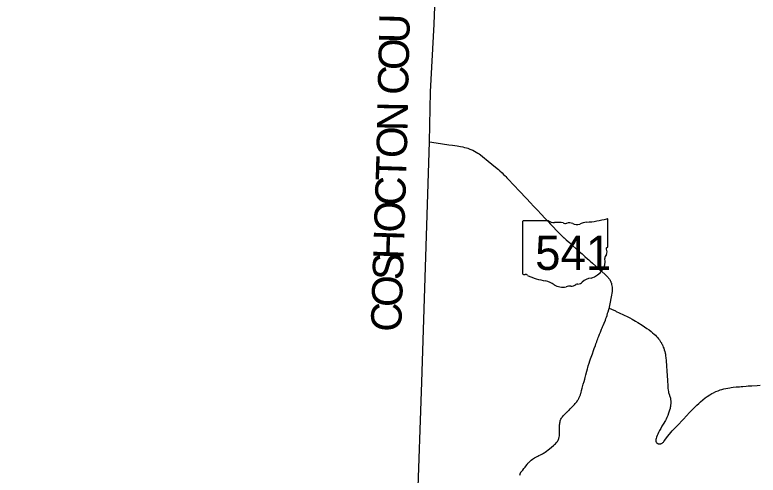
# Model space of a CAD drawing. Extents: x 1913970 to 2397567, y 78841 to 829347.
# Drawn here: x 2186978 to 2211403, y 785537 to 800656 of the extents above; entities that cross this region are included whole.
import ezdxf

# ---------------------------------------------------------------- set-up
doc = ezdxf.new("R2010")
doc.units = 0
for name, color, linetype in [('GM_X_County', 7, 'Continuous'), ('GM_X_County_Text', 7, 'Continuous'), ('GM_X_State_Location', 7, 'Continuous'), ('GM_X_State_Route', 7, 'Continuous'), ('GM_X_State_Shield', 7, 'Continuous')]:
    doc.layers.add(name, color=color, linetype=linetype)

msp = doc.modelspace()

# ---------------------------------------------------------------- linework, layer by layer
at = {"layer": 'GM_X_County'}
msp.add_lwpolyline([(2186978, 767293), (2187218, 775508), (2187296, 778812), (2187489, 783655), (2187543, 784833), (2188969, 784801), (2192356, 784732), (2196471, 784613), (2200213, 784515), (2200352, 788594), (2200607, 796487), (2200640, 798126), (2200752, 800346), (2200989, 806420)], dxfattribs=at)
at = {"layer": 'GM_X_State_Route'}
for points in [[(2200608, 796484), (2200827, 796452), (2201034, 796420), (2201242, 796389), (2201359, 796372), (2201512, 796349), (2201618, 796331), (2201696, 796316), (2201757, 796302), (2201820, 796284), (2201861, 796272), (2201905, 796257), (2201934, 796247), (2201963, 796235), (2201995, 796221), (2202023, 796208), (2202082, 796178), (2202137, 796147), (2202187, 796117), (2202234, 796086), (2202279, 796053), (2202347, 796001), (2202533, 795850), (2202772, 795655), (2202871, 795574), (2202918, 795533), (2202990, 795465), (2203039, 795417), (2203085, 795371), (2203110, 795345), (2203146, 795307), (2203420, 795015), (2203517, 794912), (2203626, 794798), (2203713, 794705), (2203811, 794599), (2203901, 794503), (2204048, 794349), (2204150, 794242), (2204271, 794113), (2204404, 793972), (2204500, 793868), (2204578, 793784), (2204675, 793682), (2204769, 793582), (2204792, 793558), (2204879, 793469), (2204956, 793393), (2205020, 793335), (2205026, 793329), (2205094, 793267), (2205212, 793163), (2205305, 793080), (2205426, 792970), (2205527, 792881), (2205618, 792801), (2205712, 792718), (2205796, 792645), (2205840, 792606), (2205887, 792565), (2205965, 792496), (2206069, 792405), (2206169, 792315), (2206256, 792235), (2206385, 792119), (2206394, 792110), (2206430, 792075), (2206464, 792040), (2206477, 792026), (2206488, 792012), (2206500, 791997), (2206510, 791983), (2206519, 791970), (2206528, 791956), (2206536, 791943), (2206542, 791929), (2206550, 791913), (2206558, 791896), (2206561, 791888)], [(2206561, 791888), (2206565, 791880), (2206571, 791862), (2206581, 791828), (2206589, 791799), (2206596, 791756), (2206602, 791711), (2206605, 791658), (2206605, 791633), (2206605, 791608), (2206603, 791566), (2206597, 791513), (2206589, 791454), (2206577, 791390), (2206530, 791165), (2206511, 791059), (2206504, 791019)], [(2203578, 785530), (2203577, 785542), (2203577, 785550), (2203578, 785561), (2203580, 785572), (2203581, 785578), (2203583, 785586), (2203586, 785592), (2203590, 785602), (2203594, 785610), (2203600, 785620), (2203609, 785632), (2203665, 785701), (2203705, 785751), (2203744, 785801), (2203770, 785835), (2203810, 785890), (2203838, 785925), (2203856, 785945), (2203879, 785966), (2203909, 785994), (2203948, 786026), (2203988, 786058), (2204018, 786079), (2204054, 786101), (2204103, 786127), (2204163, 786161), (2204200, 786178), (2204253, 786203), (2204312, 786234), (2204346, 786254), (2204373, 786272), (2204403, 786291), (2204451, 786326), (2204505, 786371), (2204542, 786401), (2204617, 786460), (2204680, 786512), (2204716, 786543), (2204745, 786570), (2204769, 786596), (2204791, 786622), (2204807, 786646), (2204823, 786670), (2204832, 786684), (2204839, 786699), (2204845, 786714), (2204850, 786726), (2204858, 786757), (2204864, 786789), (2204870, 786831), (2204871, 786875), (2204873, 786929), (2204874, 786992), (2204875, 787115), (2204879, 787185), (2204883, 787221), (2204888, 787259), (2204894, 787291), (2204902, 787322), (2204912, 787352), (2204924, 787379), (2204937, 787405), (2204952, 787429), (2204969, 787453), (2204992, 787480), (2205019, 787509), (2205096, 787585), (2205136, 787623), (2205146, 787632), (2205157, 787644), (2205174, 787659), (2205190, 787675), (2205230, 787714), (2205249, 787732), (2205271, 787756), (2205291, 787778), (2205309, 787797), (2205318, 787806), (2205369, 787861), (2205393, 787888), (2205416, 787916), (2205441, 787947), (2205460, 787974), (2205473, 787993), (2205481, 788005), (2205488, 788018), (2205499, 788036), (2205508, 788051), (2205516, 788068), (2205527, 788091), (2205544, 788134), (2205560, 788177), (2205576, 788228), (2205584, 788255), (2205602, 788315), (2205622, 788391), (2205657, 788523), (2205681, 788609), (2205703, 788690), (2205718, 788744), (2205742, 788834), (2205774, 788954), (2205792, 789025), (2205805, 789072), (2205822, 789130), (2205848, 789219), (2205868, 789287), (2205895, 789361), (2205957, 789527), (2205996, 789633), (2206018, 789696), (2206055, 789799), (2206074, 789851), (2206098, 789916), (2206116, 789965), (2206132, 790013), (2206147, 790055), (2206165, 790100), (2206181, 790139), (2206195, 790173), (2206219, 790233), (2206233, 790267), (2206259, 790330), (2206269, 790354), (2206279, 790379), (2206292, 790409), (2206311, 790457), (2206340, 790526), (2206383, 790631), (2206399, 790677), (2206419, 790731), (2206437, 790786), (2206458, 790852), (2206472, 790901), (2206494, 790980), (2206504, 791019)], [(2206504, 791019), (2206587, 790986), (2206711, 790930), (2206739, 790917), (2206831, 790873), (2206982, 790801), (2207124, 790733), (2207192, 790699), (2207261, 790662), (2207369, 790600), (2207448, 790552), (2207588, 790460), (2207749, 790353), (2207817, 790306), (2207883, 790257), (2207936, 790213), (2207984, 790173), (2208027, 790132), (2208064, 790095), (2208099, 790055), (2208132, 790014), (2208146, 789996), (2208160, 789978), (2208173, 789959), (2208185, 789940), (2208198, 789921), (2208212, 789899), (2208222, 789882), (2208231, 789865), (2208242, 789845), (2208249, 789830), (2208255, 789817), (2208261, 789803), (2208271, 789779), (2208285, 789745), (2208300, 789705), (2208318, 789652), (2208335, 789596), (2208348, 789548), (2208357, 789506), (2208364, 789460), (2208373, 789392), (2208380, 789300), (2208392, 789117), (2208402, 788963), (2208422, 788642), (2208433, 788465), (2208439, 788393), (2208447, 788328), (2208454, 788287), (2208456, 788276)], [(2208456, 788276), (2208461, 788255), (2208470, 788224), (2208477, 788202), (2208504, 788125), (2208513, 788096), (2208521, 788061), (2208524, 788044), (2208527, 788027), (2208528, 788010), (2208530, 787992), (2208531, 787949), (2208530, 787890), (2208527, 787834), (2208522, 787792), (2208517, 787759), (2208509, 787727), (2208492, 787673), (2208458, 787574), (2208430, 787500), (2208402, 787434), (2208376, 787377), (2208354, 787336), (2208335, 787302), (2208300, 787246), (2208239, 787142), (2208200, 787074), (2208162, 787004), (2208130, 786942), (2208102, 786880), (2208083, 786834), (2208066, 786789), (2208048, 786736), (2208041, 786706), (2208039, 786681), (2208040, 786665), (2208042, 786651), (2208044, 786644), (2208048, 786634), (2208053, 786622), (2208064, 786604), (2208077, 786589), (2208086, 786582), (2208095, 786576), (2208105, 786571), (2208120, 786565), (2208139, 786562), (2208159, 786560), (2208188, 786563), (2208194, 786564), (2208207, 786568), (2208218, 786571), (2208227, 786575), (2208252, 786591), (2208274, 786607), (2208290, 786621), (2208308, 786644), (2208341, 786686), (2208429, 786807), (2208490, 786885), (2208532, 786935), (2208582, 786992), (2208661, 787076), (2208740, 787159), (2208946, 787380), (2209145, 787589), (2209220, 787667), (2209291, 787740), (2209340, 787789), (2209385, 787832), (2209453, 787893), (2209514, 787948), (2209589, 788012), (2209663, 788072), (2209729, 788121), (2209815, 788177), (2209877, 788214), (2209938, 788245), (2210016, 788281), (2210089, 788311), (2210154, 788335), (2210213, 788354), (2210273, 788372), (2210341, 788387), (2210405, 788399), (2210477, 788410), (2210516, 788415), (2210581, 788422), (2210686, 788433), (2210781, 788441), (2210792, 788442), (2210849, 788446), (2210902, 788450), (2211013, 788460), (2211078, 788465), (2211193, 788474), (2211376, 788486), (2211467, 788494)]]:
    msp.add_lwpolyline(points, dxfattribs=at)
at = {"layer": 'GM_X_State_Shield'}
for p, q in [((2203661, 793860), (2203661, 792159)), ((2204510, 793889), (2203689, 793889)), ((2206463, 793042), (2206463, 793932)), ((2206463, 793042), (2206463, 793042))]:
    msp.add_line(p, q, dxfattribs=at)
for centre, major_axis, start_param, end_param in [((2203694, 793864), (32.5, 0), 1.712693, 3.28349), ((2204705, 794087), (315, 0), 4.042523, 4.731795), ((2204809, 792934), (1130, 0), 1.404758, 1.657858), ((2205066, 793873), (90.8, 0), 3.836095, 5.185415), ((2205199, 793676), (189, 0), 0.950623, 2.079405), ((2205844, 793370), (598, 0), 1.699011, 2.107814), ((2205465, 796209), (2971, 0), 4.814394, 5.042369), ((2206432, 793935), (31.2, 0), 6.141152, 7.989035), ((2205443, 793946), (227, 0), 4.081561, 5.145723), ((2206456, 792976), (48.3, 0), 1.883978, 3.671073), ((2206149, 792864), (290, 0), 5.934695, 6.695948), ((2206430, 793038), (33.4, 0), 5.05454, 6.418171), ((2205632, 792556), (743, 0), 5.101752, 6.440018), ((2206575, 792669), (211, 0), 2.387724, 3.262537), ((2203694, 792155), (32.7, 0), 3.00124, 4.508301), ((2203699, 792329), (250, 0), 4.665946, 4.897461), ((2203750, 792061), (90.1, 0), 0.519207, 1.627899), ((2204888, 793589), (2146, 0), 4.195997, 4.488961), ((2204248, 791395), (671, 0), 0.823519, 1.323587), ((2205429, 791994), (240, 0), 4.937069, 5.64225), ((2205945, 791681), (407, 0), 1.647645, 2.488434), ((2204974, 792052), (426, 0), 4.026481, 4.996735), ((2205220, 791464), (350, 0), 1.495662, 1.94098), ((2205251, 791925), (227, 0), 4.691044, 5.507374), ((2205456, 791760), (63.9, 0), 1.147584, 2.315152)]:
    msp.add_ellipse(centre, major_axis=major_axis, ratio=0.8, start_param=start_param, end_param=end_param, dxfattribs=at)

# ---------------------------------------------------------------- texts
at = {"layer": 'GM_X_County_Text'}
for s, rotation, p in [('U', 88.6368, (2199938, 799717)), ('O', 88.6499, (2199918, 798835)), ('C', 88.7376, (2199900, 798020)), ('N', 88.9622, (2199878, 796833)), ('O', 88.469, (2199854, 795941)), ('T', 88.2126, (2199831, 795190)), ('C', 88.1616, (2199804, 794374)), ('O', 88.1583, (2199776, 793492)), ('H', 88.1594, (2199748, 792610)), ('S', 88.159, (2199726, 791931)), ('O', 88.1594, (2199698, 791048)), ('C', 88.1594, (2199671, 790234))]:
    msp.add_text(s, height=1000, rotation=rotation, dxfattribs=at).set_placement(p)
at = {"layer": 'GM_X_State_Location'}
msp.add_text('541', height=1, rotation=0, dxfattribs=at).set_placement((2205258, 792442))
for s in ['s', 'r']:
    msp.add_text(s, height=1, dxfattribs=at).set_placement((2205611, 792514))
at = {"layer": 'GM_X_State_Shield'}
msp.add_text('541', height=1120.7, dxfattribs=at).set_placement((2204074, 792279))

doc.saveas('drawing.dxf')
